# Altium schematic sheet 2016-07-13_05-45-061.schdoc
size 307 x 144 mm; SheetNumber: 1; SheetTotal: 1
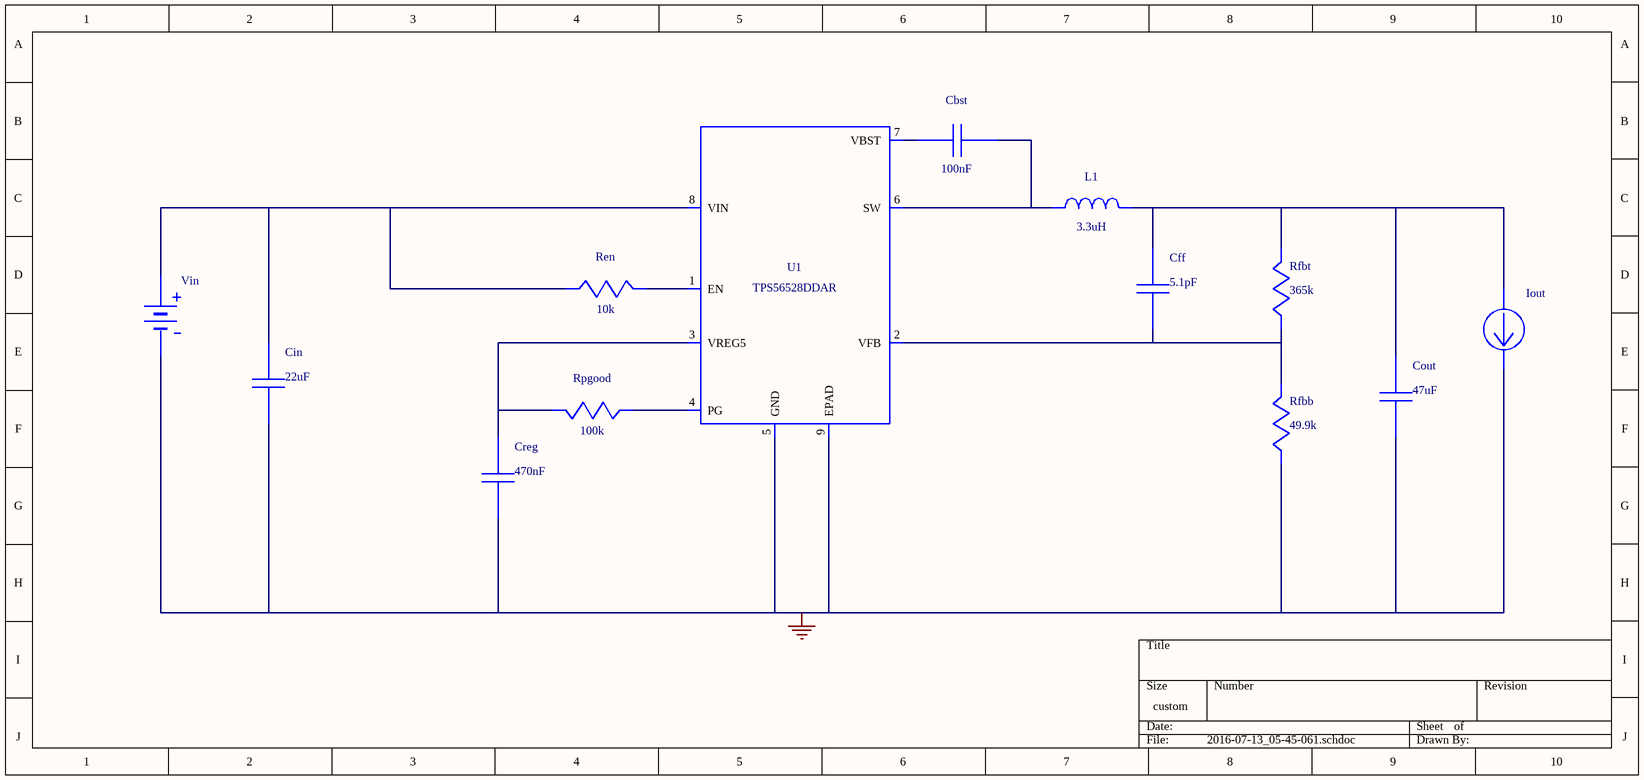
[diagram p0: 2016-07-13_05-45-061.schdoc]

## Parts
Cbst  value 100nF  (hidden comment: GRM155R61A104KA01D)
Cff  value 5.1pF  (hidden comment: GRM1555C1E5R1CA01D)
Cin  value 22uF  (hidden comment: GRM32ER61E226KE15L)
Cout  value 47uF  (hidden comment: GRM31CR61A476KE15L)
Creg  value 470nF  (hidden comment: GRM155R61A474KE15D)
Iout  WB_CURRENT_LOAD  (value not drawn)
L1  value 3.3uH  (hidden comment: SRN6045-3R3Y)
Ren  value 10k  (hidden comment: CRCW040210K0FKED)
Rfbb  value 49.9k  (hidden comment: CRCW040249K9FKED)
Rfbt  value 365k  (hidden comment: CRCW0402365KFKED)
Rpgood  value 100k  (hidden comment: CRCW0402100KFKED)
U1  TPS56528DDAR
Vin  WB_BATTERY  (value not drawn)

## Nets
0: Cin.2 Cout.2 Creg.2 Iout.2(-) Rfbb.2 U1.5(GND) U1.9(EPAD) Vin.2(-)
NetCbst_1: Cbst.1 U1.7(VBST)
NetCbst_2: Cbst.2 L1.1 U1.6(SW)
NetCff_1: Cff.1 Cout.1 Iout.1(+) L1.2 Rfbt.1
NetCff_2: Cff.2 Rfbb.1 Rfbt.2 U1.2(VFB)
NetCin_1: Cin.1 Ren.2 U1.8(VIN) Vin.1(+)
NetCreg_1: Creg.1 Rpgood.1 U1.3(VREG5)
NetRen_1: Ren.1 U1.1(EN)
NetRpgood_2: Rpgood.2 U1.4(PG)

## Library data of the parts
Cbst = GRM155R61A104KA01D: GRM155R61A104KA0; Manufacturer Name: MuRata
Cff = GRM1555C1E5R1CA01D: GRM1555C1E5R1CA0; Manufacturer Name: MuRata
Cin = GRM32ER61E226KE15L: GRM32ER61E226KE1; Manufacturer Name: MuRata
Cout = GRM31CR61A476KE15L: GRM31CR61A476KE1; Manufacturer Name: MuRata
Creg = GRM155R61A474KE15D: GRM155R61A474KE1; Manufacturer Name: MuRata
L1 = SRN6045-3R3Y: Manufacturer Name: Bourns
Ren = CRCW040210K0FKED: Manufacturer Name: Vishay-Dale
Rfbb = CRCW040249K9FKED: Manufacturer Name: Vishay-Dale
Rfbt = CRCW0402365KFKED: Manufacturer Name: Vishay-Dale
Rpgood = CRCW0402100KFKED: Manufacturer Name: Vishay-Dale
U1 = TPS56528DDAR: Manufacturer Name: Texas Instruments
